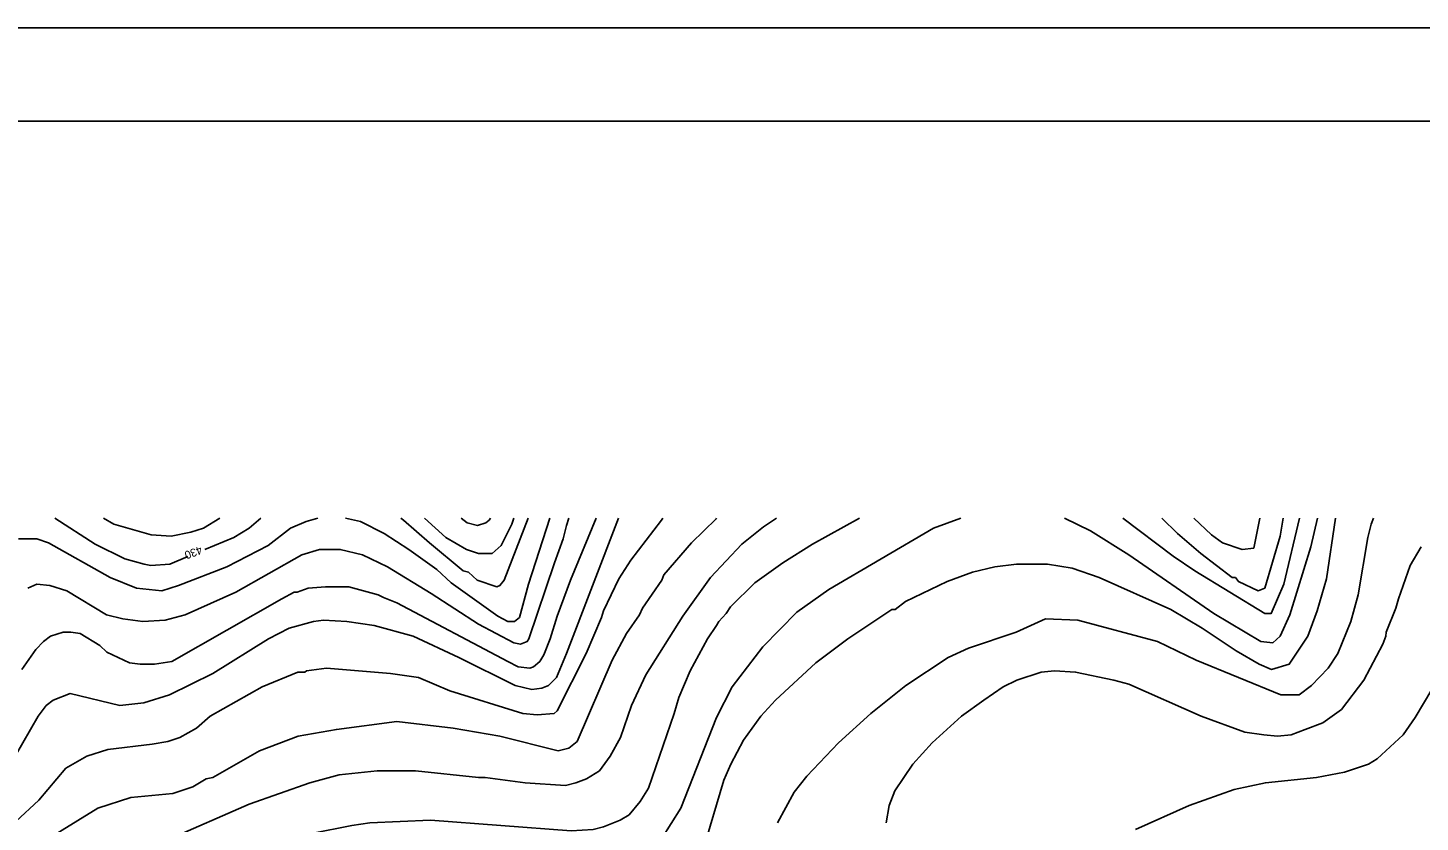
# Model space of a CAD drawing. Extents: x -510989 to -501240, y -1184665 to -1176089.
# Drawn here: x -510315 to -509271, y -1176694 to -1176098 of the extents above; entities that cross this region are included whole.
import ezdxf

# ---------------------------------------------------------------- set-up
doc = ezdxf.new("R2010")
doc.units = 0
for name, color, linetype in [('rozpiska', 7, 'Continuous'), ('vrstevnice_01', 7, 'Continuous'), ('vrstevnice_02', 7, 'Continuous'), ('vrstevnice_04', 7, 'Continuous')]:
    doc.layers.add(name, color=color, linetype=linetype)

msp = doc.modelspace()

# ---------------------------------------------------------------- linework, layer by layer
at = {"layer": 'rozpiska'}
for points in [[(-508019.09, -1176098), (-508019.09, -1184498), (-510989.09, -1184498), (-510989.09, -1176098)], [(-508089.09, -1176168), (-508089.09, -1184428), (-510919.09, -1184428), (-510919.09, -1176168)]]:
    msp.add_lwpolyline(points, close=True, dxfattribs=at)
at = {"layer": 'vrstevnice_01'}
for points in [[(-510324.19, -1176644), (-510306.91, -1176614), (-510300.91, -1176606), (-510295.69, -1176602), (-510283, -1176597), (-510245.81, -1176606), (-510227.81, -1176604), (-510208.59, -1176598), (-510175.91, -1176582), (-510134.31, -1176556), (-510118.69, -1176548), (-510100.41, -1176543), (-510093, -1176542), (-510075.41, -1176543), (-510055.09, -1176546), (-510025.69, -1176554), (-509991.59, -1176570), (-509949.19, -1176591), (-509936.91, -1176594), (-509929.19, -1176593), (-509924.41, -1176591), (-509918.19, -1176585), (-509910.91, -1176567), (-509871.94, -1176465.53)], [(-509798.3, -1176465.53), (-509798.69, -1176466), (-509817, -1176484), (-509837.91, -1176508), (-509839.31, -1176512), (-509853.91, -1176533), (-509856.19, -1176538), (-509865.81, -1176552), (-509876.5, -1176572), (-509902.91, -1176633), (-509909.09, -1176638), (-509917.09, -1176640), (-509960.81, -1176629), (-509995.81, -1176623), (-510038.09, -1176618), (-510083.31, -1176624), (-510111.91, -1176629), (-510140.91, -1176640), (-510176.09, -1176660), (-510181.09, -1176661), (-510191, -1176667), (-510206.09, -1176672), (-510237.5, -1176675), (-510262.19, -1176683), (-510318.91, -1176718)], [(-509909.08, -1176465.53), (-509910.91, -1176471), (-509913.31, -1176481), (-509919.91, -1176499), (-509939, -1176556), (-509940.19, -1176558), (-509945.31, -1176560), (-509950.31, -1176559), (-509976.91, -1176545), (-510012.19, -1176522), (-510044.91, -1176502), (-510063.81, -1176493), (-510080.41, -1176489), (-510096.09, -1176489), (-510109.19, -1176493), (-510158.69, -1176521), (-510196.81, -1176538), (-510211.69, -1176542), (-510228.41, -1176543), (-510243.41, -1176541), (-510255.59, -1176538), (-510285.5, -1176520), (-510298.09, -1176516), (-510307.91, -1176515), (-510314.69, -1176518)], [(-510194.62, -1176494.29), (-510208.31, -1176500), (-510222.41, -1176501), (-510227.41, -1176500), (-510242, -1176496), (-510264.31, -1176485), (-510294.57, -1176465.53)], [(-510139.96, -1176465.53), (-510148.69, -1176473), (-510160.31, -1176480), (-510181.96, -1176489.02)], [(-509939.52, -1176465.53), (-509957.5, -1176512), (-509960.69, -1176516), (-509963, -1176517), (-509977.81, -1176512), (-509984.41, -1176506), (-509988.31, -1176505), (-510013.41, -1176484), (-510033, -1176467), (-510034.99, -1176465.53)], [(-509989.78, -1176465.53), (-509985.19, -1176469), (-509977.59, -1176471), (-509971.41, -1176469), (-509968.69, -1176467), (-509967.7, -1176465.53)], [(-509691.17, -1176465.53), (-509726.31, -1176485), (-509748.59, -1176499), (-509769.59, -1176514), (-509787.81, -1176532), (-509791.09, -1176537), (-509796.59, -1176543), (-509798.31, -1176546), (-509805.19, -1176556), (-509818.09, -1176580), (-509826.69, -1176600), (-509830, -1176612), (-509849.31, -1176668), (-509855.5, -1176678), (-509863.81, -1176688), (-509870.69, -1176692), (-509883.09, -1176697), (-509890.81, -1176699), (-509907.19, -1176700)], [(-509808.69, -1176715), (-509792.81, -1176662), (-509787.59, -1176650), (-509778.09, -1176632), (-509765.09, -1176614), (-509754, -1176602), (-509723.81, -1176574), (-509699.91, -1176556), (-509667, -1176534), (-509664.5, -1176534), (-509656.59, -1176528), (-509625.5, -1176513), (-509606.5, -1176506), (-509589.59, -1176502), (-509573.5, -1176500), (-509550.09, -1176500), (-509531.69, -1176503), (-509511.31, -1176510), (-509457.81, -1176534), (-509434.09, -1176548), (-509408.81, -1176565), (-509391.5, -1176575), (-509382.31, -1176579), (-509368.91, -1176575), (-509355.09, -1176554), (-509348, -1176535), (-509341, -1176511), (-509334.32, -1176465.53)], [(-509361.14, -1176465.53), (-509372.91, -1176515), (-509382.41, -1176537), (-509387.19, -1176537), (-509439.59, -1176505), (-509455.91, -1176494), (-509493.61, -1176465.53)], [(-509390.85, -1176465.53), (-509395.5, -1176488), (-509404.31, -1176489), (-509418.91, -1176484), (-509427.31, -1176478), (-509440.41, -1176465.53)], [(-509671.19, -1176694), (-509668.81, -1176681), (-509664.59, -1176670), (-509651.09, -1176650), (-509636.69, -1176634), (-509614.69, -1176614), (-509598, -1176602), (-509583.41, -1176592), (-509573.09, -1176587), (-509554.81, -1176581), (-509544.91, -1176580), (-509529.09, -1176581), (-509500.41, -1176587), (-509489.09, -1176590), (-509434.91, -1176614), (-509402.19, -1176626), (-509387.91, -1176628), (-509377.81, -1176629), (-509367.5, -1176628), (-509357.09, -1176624), (-509343.81, -1176619), (-509329.81, -1176609), (-509312.91, -1176587), (-509298.81, -1176560), (-509296.41, -1176554), (-509296.19, -1176551), (-509289.09, -1176533), (-509287.09, -1176526), (-509278.19, -1176501), (-509270.09, -1176487)], [(-509907.19, -1176700), (-510012.69, -1176692), (-510058.19, -1176694), (-510071.69, -1176696), (-510101.91, -1176702), (-510128.69, -1176709), (-510172.41, -1176723), (-510203.91, -1176735), (-510248.59, -1176744), (-510273.09, -1176753), (-510287.59, -1176761), (-510300.69, -1176771), (-510314.09, -1176783), (-510326.91, -1176797)]]:
    msp.add_lwpolyline(points, dxfattribs=at)
at = {"layer": 'vrstevnice_02'}
for points in [[(-509615.23, -1176465.53), (-509635.69, -1176473), (-509714, -1176519), (-509738.19, -1176536), (-509763.69, -1176562), (-509786.69, -1176592), (-509798.31, -1176615), (-509825.09, -1176683), (-509839.59, -1176706), (-509843.31, -1176710), (-509855.59, -1176717), (-509876.09, -1176727), (-509898.5, -1176734), (-509926.41, -1176736), (-509948.91, -1176736), (-510043, -1176727), (-510067.41, -1176728), (-510101.59, -1176733), (-510261.59, -1176782), (-510278.31, -1176790), (-510295.59, -1176802), (-510308.41, -1176812), (-510326.19, -1176832)], [(-510323.69, -1176693), (-510306.41, -1176677), (-510286.19, -1176653), (-510270.5, -1176644), (-510254.81, -1176639), (-510221.41, -1176635), (-510209.81, -1176633), (-510200.69, -1176630), (-510188.19, -1176623), (-510177.91, -1176614), (-510138.91, -1176592), (-510112.19, -1176581), (-510107.09, -1176581), (-510105.69, -1176580), (-510090.81, -1176578), (-510042.81, -1176582), (-510021.81, -1176585), (-509998.41, -1176595), (-509943.5, -1176612), (-509932.91, -1176613), (-509920.09, -1176612), (-509917.91, -1176610), (-509896.09, -1176567), (-509884.5, -1176540), (-509883.09, -1176535), (-509871.59, -1176511), (-509862.69, -1176497), (-509839.69, -1176467), (-509838.62, -1176465.53)], [(-510321.59, -1176481), (-510308, -1176481), (-510299.09, -1176484), (-510252.91, -1176510), (-510233.31, -1176518), (-510214.19, -1176520), (-510201.69, -1176516), (-510165.59, -1176502), (-510134.5, -1176486), (-510117.81, -1176473), (-510105.91, -1176468), (-510097.33, -1176465.53)], [(-510319.19, -1176579), (-510308.59, -1176564), (-510303, -1176558), (-510297.81, -1176554), (-510288.09, -1176551), (-510282.5, -1176551), (-510275.41, -1176552), (-510260.69, -1176561), (-510255.41, -1176566), (-510238.59, -1176574), (-510230.5, -1176575), (-510219.81, -1176575), (-510206.81, -1176573), (-510124.31, -1176526), (-510115, -1176521), (-510112.81, -1176521), (-510104.59, -1176518), (-510091.5, -1176517), (-510073.91, -1176517), (-510051.91, -1176523), (-510048, -1176525), (-510037.91, -1176529), (-509954.91, -1176573), (-509947, -1176577), (-509938.41, -1176578), (-509935.59, -1176577), (-509930.91, -1176573), (-509927.91, -1176568), (-509923, -1176556), (-509917.69, -1176539), (-509907.69, -1176512), (-509888.49, -1176465.53)], [(-510170.79, -1176465.53), (-510183.09, -1176473), (-510192.59, -1176476), (-510207.19, -1176479), (-510222.19, -1176478), (-510250.09, -1176470), (-510258.04, -1176465.53)], [(-510210.41, -1176707), (-510148.81, -1176680), (-510103.31, -1176664), (-510081.19, -1176658), (-510052.81, -1176655), (-510024.09, -1176655), (-509976.81, -1176660), (-509971.91, -1176660), (-509941.81, -1176664), (-509911.5, -1176666), (-509903.81, -1176664), (-509895.91, -1176661), (-509886.19, -1176655), (-509878.09, -1176644), (-509870.41, -1176630), (-509862, -1176606), (-509851.41, -1176583), (-509823.69, -1176539), (-509802.91, -1176510), (-509779.31, -1176485), (-509763.09, -1176472), (-509753.36, -1176465.53)], [(-510076.59, -1176465.53), (-510065.31, -1176468), (-510047.5, -1176477), (-510029.09, -1176489), (-510008.09, -1176504), (-509997.19, -1176514), (-509962.19, -1176539), (-509954.91, -1176543), (-509949.81, -1176543), (-509946, -1176540), (-509939.19, -1176515), (-509923.38, -1176465.53)], [(-509950.38, -1176465.53), (-509951.91, -1176470), (-509959.69, -1176486), (-509966.5, -1176492), (-509976.69, -1176492), (-509985.81, -1176489), (-510001.31, -1176480), (-510017.18, -1176465.53)], [(-509305.79, -1176465.53), (-509307.5, -1176470), (-509309.91, -1176480), (-509317.31, -1176523), (-509322.69, -1176543), (-509332.41, -1176567), (-509339.69, -1176578), (-509352.31, -1176591), (-509361.41, -1176598), (-509375.09, -1176598), (-509438.81, -1176572), (-509467.69, -1176558), (-509527.41, -1176542), (-509551.59, -1176541), (-509573.69, -1176551), (-509609.31, -1176563), (-509624.59, -1176570), (-509656.5, -1176591), (-509682.69, -1176612), (-509706.81, -1176634), (-509730.59, -1176659), (-509740.19, -1176671), (-509752.5, -1176694)], [(-509347.73, -1176465.53), (-509352.69, -1176487), (-509368.5, -1176538), (-509375.81, -1176554), (-509381.31, -1176559), (-509390.09, -1176558), (-509425.41, -1176537), (-509489.09, -1176493), (-509517.81, -1176475), (-509537.41, -1176465.53)], [(-509464.49, -1176465.53), (-509452.81, -1176477), (-509435.19, -1176492), (-509411.81, -1176510), (-509409.31, -1176510), (-509407, -1176513), (-509392.31, -1176520), (-509387.31, -1176518), (-509375.81, -1176479), (-509373.5, -1176465.53)], [(-509261.91, -1176594), (-509274.5, -1176615), (-509283.59, -1176628), (-509303, -1176646), (-509309.59, -1176650), (-509327.59, -1176656), (-509348.59, -1176660), (-509386.81, -1176664), (-509410.09, -1176669), (-509443.91, -1176681), (-509484.09, -1176699)]]:
    msp.add_lwpolyline(points, dxfattribs=at)

# ---------------------------------------------------------------- texts
at = {"layer": 'vrstevnice_04'}
msp.add_text('430', height=6, rotation=200.13501, dxfattribs=at).set_placement((-510185.21, -1176486.31))

doc.saveas('drawing.dxf')
